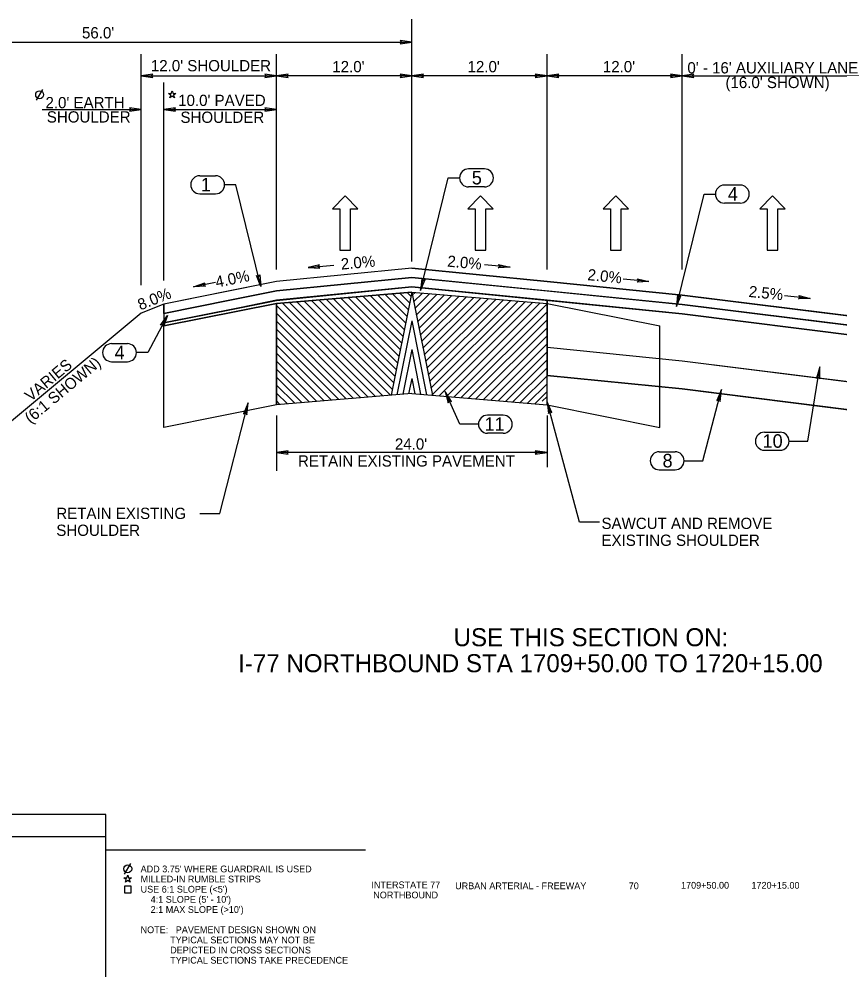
# Model space of a CAD drawing. Extents: x 2003207 to 2014043, y 843846 to 860154.
# Drawn here: x 2013648 to 2013720.8, y 844806 to 844891 of the extents above; entities that cross this region are included whole.
import ezdxf

# ---------------------------------------------------------------- set-up
doc = ezdxf.new("R2010")
doc.units = 0
for name, color, linetype in [('RD_EX_Road', 7, 'Continuous'), ('RD_EX_Road_txCode', 7, 'Continuous'), ('RD_QTY_Base_Course', 7, 'Continuous'), ('RD_QTY_ConcPave', 7, 'Continuous'), ('RD_QTY_Intermediate', 7, 'Continuous'), ('RD_QTY_PermVeg', 7, 'Continuous'), ('RD_QTY_Surf_Course', 7, 'Continuous'), ('RD_SHT_Bndy', 7, 'Continuous'), ('RD_SHT_TX', 7, 'Continuous'), ('RD_TX_Misc2', 7, 'Continuous'), ('RD_TX_TypSect', 7, 'Continuous')]:
    doc.layers.add(name, color=color, linetype=linetype)

msp = doc.modelspace()

# ---------------------------------------------------------------- linework, layer by layer
at = {"layer": 'RD_EX_Road'}
for p, q in [((2013682.86, 844866.75), (2013670.86, 844865.75)), ((2013682.86, 844867.226), (2013679.704, 844866.91)), ((2013680.493, 844866.553), (2013682.432, 844864.613)), ((2013682.86, 844866.75), (2013681.03, 844857.602)), ((2013681.145, 844866.607), (2013682.55, 844865.202)), ((2013681.798, 844866.662), (2013682.668, 844865.792)), ((2013682.451, 844866.716), (2013682.786, 844866.381)), ((2013682.86, 844866.75), (2013684.689, 844857.602)), ((2013682.86, 844866.75), (2013694.86, 844865.75)), ((2013682.913, 844866.483), (2013683.156, 844866.725)), ((2013683.031, 844865.894), (2013683.809, 844866.671)), ((2013683.149, 844865.304), (2013684.461, 844866.617)), ((2013683.267, 844864.715), (2013685.114, 844866.562)), ((2013670.86, 844865.75), (2013660.86, 844863.75)), ((2013670.86, 844856.754), (2013670.86, 844865.75)), ((2013671.355, 844865.791), (2013679.658, 844857.487)), ((2013672.007, 844865.846), (2013680.311, 844857.542)), ((2013672.66, 844865.9), (2013680.964, 844857.596)), ((2013673.313, 844865.955), (2013681.136, 844858.131)), ((2013673.965, 844866.009), (2013681.254, 844858.721)), ((2013674.618, 844866.063), (2013681.372, 844859.31)), ((2013675.271, 844866.118), (2013681.49, 844859.899)), ((2013675.924, 844866.172), (2013681.607, 844860.488)), ((2013676.576, 844866.226), (2013681.725, 844861.078)), ((2013677.229, 844866.281), (2013681.843, 844861.667)), ((2013677.882, 844866.335), (2013681.961, 844862.256)), ((2013678.534, 844866.39), (2013682.079, 844862.845)), ((2013679.187, 844866.444), (2013682.197, 844863.435)), ((2013679.84, 844866.498), (2013682.315, 844864.024)), ((2013683.385, 844864.126), (2013685.767, 844866.508)), ((2013683.503, 844863.537), (2013686.419, 844866.453)), ((2013683.62, 844862.947), (2013687.072, 844866.399)), ((2013683.738, 844862.358), (2013687.725, 844866.345)), ((2013683.856, 844861.769), (2013688.378, 844866.29)), ((2013683.974, 844861.179), (2013689.03, 844866.236)), ((2013684.092, 844860.59), (2013689.683, 844866.182)), ((2013684.21, 844860.001), (2013690.336, 844866.127)), ((2013684.327, 844859.412), (2013690.988, 844866.073)), ((2013684.445, 844858.822), (2013691.641, 844866.018)), ((2013684.563, 844858.233), (2013692.294, 844865.964)), ((2013684.681, 844857.644), (2013692.947, 844865.91)), ((2013685.295, 844857.551), (2013693.599, 844865.855)), ((2013685.935, 844857.483), (2013694.252, 844865.801)), ((2013686.601, 844857.442), (2013694.905, 844865.746)), ((2013694.86, 844856.754), (2013694.86, 844865.75)), ((2013694.86, 844865.75), (2013704.86, 844863.75)), ((2013670.86, 844865.579), (2013679.006, 844857.433)), ((2013670.86, 844864.872), (2013678.353, 844857.379)), ((2013687.254, 844857.388), (2013694.86, 844864.994)), ((2013670.86, 844864.165), (2013677.7, 844857.324)), ((2013682.86, 844864.201), (2013681.549, 844857.645)), ((2013682.86, 844864.201), (2013684.171, 844857.645)), ((2013687.906, 844857.334), (2013694.86, 844864.287)), ((2013660.86, 844854.754), (2013660.86, 844863.75)), ((2013670.86, 844863.458), (2013677.048, 844857.27)), ((2013688.559, 844857.279), (2013694.86, 844863.58)), ((2013704.86, 844854.754), (2013704.86, 844863.75)), ((2013670.86, 844862.751), (2013676.395, 844857.215)), ((2013689.212, 844857.225), (2013694.86, 844862.873)), ((2013670.86, 844862.044), (2013675.742, 844857.161)), ((2013682.86, 844861.651), (2013682.067, 844857.688)), ((2013682.86, 844861.651), (2013683.652, 844857.688)), ((2013689.864, 844857.171), (2013694.86, 844862.166)), ((2013690.517, 844857.116), (2013694.86, 844861.459)), ((2013670.86, 844861.336), (2013675.089, 844857.107)), ((2013670.86, 844860.629), (2013674.437, 844857.052)), ((2013691.17, 844857.062), (2013694.86, 844860.752)), ((2013670.86, 844859.922), (2013673.784, 844856.998)), ((2013691.823, 844857.007), (2013694.86, 844860.045)), ((2013670.86, 844859.215), (2013673.131, 844856.944)), ((2013682.86, 844859.102), (2013682.586, 844857.731)), ((2013682.86, 844859.102), (2013683.134, 844857.731)), ((2013692.475, 844856.953), (2013694.86, 844859.337)), ((2013670.86, 844858.508), (2013672.479, 844856.889)), ((2013693.128, 844856.899), (2013694.86, 844858.63)), ((2013670.86, 844857.801), (2013671.826, 844856.835)), ((2013682.86, 844857.754), (2013670.86, 844856.754)), ((2013682.86, 844857.754), (2013694.86, 844856.754)), ((2013693.781, 844856.844), (2013694.86, 844857.923)), ((2013694.433, 844857.065), (2013694.86, 844857.491)), ((2013670.86, 844856.754), (2013660.86, 844854.754)), ((2013670.86, 844857.094), (2013671.173, 844856.78)), ((2013694.86, 844856.754), (2013704.86, 844854.754))]:
    msp.add_line(p, q, dxfattribs=at)
msp.add_lwpolyline([(2013660.86, 844863.75), (2013670.86, 844865.75), (2013670.86, 844856.754), (2013660.86, 844854.754)], close=True, dxfattribs=at)
at = {"layer": 'RD_EX_Road_txCode'}
msp.add_line((2013657.384, 844815.107), (2013657.95, 844816.05), dxfattribs=at)
for points in [[(2013657.335, 844814.786), (2013657.589, 844814.786), (2013657.667, 844815.028), (2013657.746, 844814.786), (2013658, 844814.786), (2013657.795, 844814.637), (2013657.873, 844814.395), (2013657.667, 844814.544), (2013657.462, 844814.395), (2013657.54, 844814.637)], [(2013657.367, 844813.452), (2013657.967, 844813.452), (2013657.967, 844814.052), (2013657.367, 844814.052)]]:
    msp.add_lwpolyline(points, close=True, dxfattribs=at)
msp.add_circle((2013657.667, 844815.578), 0.35, dxfattribs=at)
at = {"layer": 'RD_QTY_Base_Course'}
for p, q in [((2013694.86, 844861.859), (2013694.86, 844859.359)), ((2013694.86, 844859.359), (2013706.86, 844858.159)), ((2013706.86, 844858.159), (2013722.86, 844856.159))]:
    msp.add_line(p, q, dxfattribs=at)
msp.add_lwpolyline([(2013694.86, 844861.859), (2013706.86, 844860.659), (2013722.86, 844858.659), (2013735.36, 844856.159), (2013735.36, 844853.659), (2013722.86, 844856.159), (2013706.86, 844858.159), (2013694.86, 844859.359)], close=True, dxfattribs=at)
at = {"layer": 'RD_QTY_ConcPave'}
for p, q in [((2013694.86, 844867.692), (2013706.86, 844866.492)), ((2013660.86, 844865.692), (2013660.86, 844864.025)), ((2013694.86, 844861.859), (2013706.86, 844860.659)), ((2013706.86, 844860.659), (2013722.86, 844858.659))]:
    msp.add_line(p, q, dxfattribs=at)
msp.add_lwpolyline([(2013694.86, 844866.026), (2013694.86, 844861.859), (2013706.86, 844860.659), (2013722.86, 844858.659), (2013734.86, 844856.259), (2013734.86, 844860.425), (2013722.86, 844862.826), (2013706.86, 844864.826)], close=True, dxfattribs=at)
at = {"layer": 'RD_QTY_Intermediate'}
for p, q in [((2013682.86, 844868.059), (2013670.86, 844866.859)), ((2013682.86, 844868.059), (2013694.86, 844866.859)), ((2013670.86, 844866.859), (2013660.86, 844864.859)), ((2013682.86, 844867.226), (2013670.86, 844866.026)), ((2013682.86, 844866.75), (2013670.86, 844865.75)), ((2013682.86, 844867.226), (2013694.86, 844866.026)), ((2013682.86, 844866.75), (2013694.86, 844865.75)), ((2013694.86, 844866.859), (2013706.86, 844865.659)), ((2013670.86, 844866.025), (2013660.86, 844864.025)), ((2013670.86, 844865.75), (2013660.86, 844863.75)), ((2013670.86, 844865.75), (2013670.86, 844865.75)), ((2013694.86, 844866.026), (2013694.86, 844865.75)), ((2013694.86, 844866.026), (2013706.86, 844864.826)), ((2013660.86, 844864.859), (2013660.86, 844864.025)), ((2013706.86, 844865.659), (2013722.86, 844863.659)), ((2013660.86, 844864.025), (2013660.86, 844863.75)), ((2013706.86, 844864.826), (2013722.86, 844862.826))]:
    msp.add_line(p, q, dxfattribs=at)
for points in [[(2013670.86, 844866.025), (2013682.86, 844867.226), (2013706.86, 844864.826), (2013722.86, 844862.826), (2013734.86, 844860.425), (2013734.86, 844861.259), (2013722.86, 844863.659), (2013706.86, 844865.659), (2013682.86, 844868.059), (2013670.86, 844866.859), (2013666.86, 844866.059), (2013660.86, 844864.859), (2013660.86, 844864.026), (2013666.86, 844865.225)], [(2013670.86, 844865.75), (2013682.86, 844866.75), (2013694.86, 844865.75), (2013694.86, 844866.026), (2013682.86, 844867.226), (2013670.86, 844866.026), (2013666.86, 844865.226), (2013660.86, 844864.026), (2013660.86, 844863.75)]]:
    msp.add_lwpolyline(points, close=True, dxfattribs=at)
at = {"layer": 'RD_QTY_PermVeg'}
for p, q in [((2013658.86, 844864.892), (2013626.86, 844838.225)), ((2013660.86, 844865.692), (2013658.86, 844864.892))]:
    msp.add_line(p, q, dxfattribs=at)
at = {"layer": 'RD_QTY_Surf_Course'}
for p, q in [((2013682.86, 844868.892), (2013670.86, 844867.692)), ((2013682.86, 844868.892), (2013694.86, 844867.692)), ((2013670.86, 844867.692), (2013660.86, 844865.692)), ((2013706.86, 844866.492), (2013722.86, 844864.492)), ((2013660.86, 844864.859), (2013660.86, 844865.692))]:
    msp.add_line(p, q, dxfattribs=at)
msp.add_lwpolyline([(2013694.86, 844866.859), (2013706.86, 844865.659), (2013722.86, 844863.659), (2013734.86, 844861.259), (2013734.86, 844862.092), (2013722.86, 844864.492), (2013706.86, 844866.492), (2013694.86, 844867.692), (2013682.86, 844868.892), (2013670.86, 844867.692), (2013666.86, 844866.892), (2013660.86, 844865.692), (2013660.86, 844864.859), (2013666.86, 844866.059), (2013670.86, 844866.859), (2013682.86, 844868.059)], close=True, dxfattribs=at)
at = {"layer": 'RD_SHT_Bndy'}
for p, q in [((2013655.721, 844820.41), (2013615.721, 844820.41)), ((2013655.721, 844818.41), (2013655.721, 844820.41)), ((2013655.721, 844818.41), (2013615.721, 844818.41)), ((2013655.721, 844805.992), (2013655.721, 844818.41)), ((2013678.755, 844817.242), (2013655.755, 844817.242))]:
    msp.add_line(p, q, dxfattribs=at)
at = {"layer": 'RD_TX_Misc2'}
for p, q in [((2013689.304, 844877.692), (2013687.904, 844877.692)), ((2013664.06, 844877.077), (2013665.46, 844877.077)), ((2013689.304, 844876.092), (2013687.904, 844876.092)), ((2013711.998, 844876.255), (2013710.598, 844876.255)), ((2013664.06, 844875.477), (2013665.46, 844875.477)), ((2013711.998, 844874.655), (2013710.598, 844874.655)), ((2013656.233, 844862.182), (2013657.633, 844862.182)), ((2013656.233, 844860.582), (2013657.633, 844860.582)), ((2013690.98, 844855.835), (2013689.58, 844855.835)), ((2013690.98, 844854.235), (2013689.58, 844854.235)), ((2013714.144, 844854.326), (2013715.544, 844854.326)), ((2013704.821, 844852.585), (2013706.221, 844852.585)), ((2013714.144, 844852.726), (2013715.544, 844852.726)), ((2013704.821, 844850.985), (2013706.221, 844850.985))]:
    msp.add_line(p, q, dxfattribs=at)
for centre, start, end in [((2013687.904, 844876.892), 90, 270), ((2013689.304, 844876.892), 270, 90), ((2013664.06, 844876.277), 90, 270), ((2013665.46, 844876.277), 270, 90), ((2013710.598, 844875.455), 90, 270), ((2013711.998, 844875.455), 270, 90), ((2013656.233, 844861.382), 90, 270), ((2013657.633, 844861.382), 270, 90), ((2013689.58, 844855.035), 90, 270), ((2013690.98, 844855.035), 270, 90), ((2013714.144, 844853.526), 90, 270), ((2013715.544, 844853.526), 270, 90), ((2013704.821, 844851.785), 90, 270), ((2013706.221, 844851.785), 270, 90)]:
    msp.add_arc(centre, 0.8, start, end, dxfattribs=at)
at = {"layer": 'RD_TX_TypSect'}
for p, q in [((2013682.86, 844869.482), (2013682.86, 844890.976)), ((2013626.86, 844888.924), (2013682.86, 844888.924)), ((2013658.86, 844867.384), (2013658.86, 844887.863)), ((2013670.86, 844868.751), (2013670.86, 844887.863)), ((2013694.86, 844868.751), (2013694.86, 844887.863)), ((2013706.86, 844868.751), (2013706.86, 844887.863)), ((2013658.86, 844885.956), (2013670.86, 844885.956)), ((2013660.86, 844867.787), (2013660.86, 844885.363)), ((2013682.86, 844885.956), (2013670.86, 844885.956)), ((2013670.86, 844885.956), (2013670.86, 844885.956)), ((2013694.86, 844885.956), (2013682.86, 844885.956)), ((2013706.86, 844885.956), (2013694.86, 844885.956)), ((2013706.86, 844885.956), (2013722.86, 844885.956)), ((2013649.566, 844883.794), (2013650.132, 844884.737)), ((2013650.073, 844882.956), (2013658.86, 844882.956)), ((2013660.86, 844882.956), (2013670.86, 844882.956)), ((2013673.669, 844868.938), (2013675.948, 844869.146)), ((2013691.584, 844868.965), (2013689.305, 844869.173)), ((2013665.461, 844867.607), (2013663.51, 844867.217)), ((2013703.894, 844867.685), (2013701.618, 844867.912)), ((2013718.212, 844866.191), (2013715.936, 844866.419)), ((2013670.86, 844855.813), (2013670.86, 844850.894)), ((2013694.86, 844855.813), (2013694.86, 844851.208)), ((2013694.86, 844852.526), (2013670.86, 844852.526))]:
    msp.add_line(p, q, dxfattribs=at)
for points in [[(2013682.86, 844888.924), (2013681.821, 844889.074), (2013681.981, 844888.924), (2013681.821, 844888.775)], [(2013658.86, 844885.956), (2013659.898, 844885.806), (2013659.739, 844885.956), (2013659.898, 844886.106)], [(2013670.86, 844885.956), (2013669.821, 844886.106), (2013669.981, 844885.956), (2013669.821, 844885.806)], [(2013670.86, 844885.956), (2013671.898, 844885.806), (2013671.739, 844885.956), (2013671.898, 844886.106)], [(2013682.86, 844885.956), (2013681.821, 844886.106), (2013681.981, 844885.956), (2013681.821, 844885.806)], [(2013682.86, 844885.956), (2013683.898, 844885.806), (2013683.739, 844885.956), (2013683.898, 844886.106)], [(2013694.86, 844885.956), (2013693.821, 844886.106), (2013693.981, 844885.956), (2013693.821, 844885.806)], [(2013694.86, 844885.956), (2013695.898, 844885.806), (2013695.739, 844885.956), (2013695.898, 844886.106)], [(2013706.86, 844885.956), (2013705.821, 844886.106), (2013705.981, 844885.956), (2013705.821, 844885.806)], [(2013706.86, 844885.956), (2013707.898, 844885.806), (2013707.739, 844885.956), (2013707.898, 844886.106)], [(2013661.275, 844884.383), (2013661.529, 844884.383), (2013661.608, 844884.625), (2013661.686, 844884.383), (2013661.941, 844884.383), (2013661.735, 844884.234), (2013661.814, 844883.992), (2013661.608, 844884.141), (2013661.402, 844883.992), (2013661.481, 844884.234)], [(2013658.86, 844882.956), (2013657.821, 844883.106), (2013657.981, 844882.956), (2013657.821, 844882.806)], [(2013660.86, 844882.956), (2013661.898, 844882.806), (2013661.739, 844882.956), (2013661.898, 844883.106)], [(2013670.86, 844882.956), (2013669.821, 844883.106), (2013669.981, 844882.956), (2013669.821, 844882.806)], [(2013676.482, 844870.484), (2013677.442, 844870.484), (2013677.442, 844874.153), (2013678.093, 844874.153), (2013676.962, 844875.284), (2013675.83, 844874.153), (2013676.482, 844874.153)], [(2013688.482, 844870.484), (2013689.442, 844870.484), (2013689.442, 844874.153), (2013690.093, 844874.153), (2013688.962, 844875.284), (2013687.83, 844874.153), (2013688.482, 844874.153)], [(2013700.482, 844870.484), (2013701.442, 844870.484), (2013701.442, 844874.153), (2013702.093, 844874.153), (2013700.962, 844875.284), (2013699.83, 844874.153), (2013700.482, 844874.153)], [(2013714.38, 844870.484), (2013715.34, 844870.484), (2013715.34, 844874.153), (2013715.991, 844874.153), (2013714.86, 844875.284), (2013713.728, 844874.153), (2013714.38, 844874.153)], [(2013673.669, 844868.938), (2013674.717, 844868.883), (2013674.544, 844869.018), (2013674.69, 844869.182)], [(2013691.584, 844868.965), (2013690.535, 844868.911), (2013690.708, 844869.045), (2013690.563, 844869.209)], [(2013669.477, 844867.257), (2013669.084, 844868.231), (2013669.268, 844868.111), (2013669.375, 844868.302)], [(2013663.51, 844867.217), (2013664.499, 844867.567), (2013664.372, 844867.389), (2013664.558, 844867.273)], [(2013683.65, 844866.902), (2013684.043, 844867.875), (2013683.859, 844867.755), (2013683.751, 844867.946)], [(2013703.894, 844867.685), (2013702.846, 844867.639), (2013703.02, 844867.772), (2013702.876, 844867.937)], [(2013706.344, 844865.464), (2013706.736, 844866.437), (2013706.553, 844866.318), (2013706.445, 844866.509)], [(2013718.212, 844866.191), (2013717.164, 844866.145), (2013717.338, 844866.279), (2013717.194, 844866.444)], [(2013661.181, 844864.681), (2013660.829, 844863.692), (2013660.771, 844863.903), (2013660.564, 844863.832)], [(2013719.071, 844860.12), (2013718.758, 844859.118), (2013718.931, 844859.252), (2013719.054, 844859.07)], [(2013710.349, 844858.101), (2013709.939, 844857.135), (2013710.125, 844857.251), (2013710.229, 844857.059)], [(2013685.817, 844857.927), (2013686.102, 844856.918), (2013686.174, 844857.125), (2013686.376, 844857.04)], [(2013668.35, 844856.918), (2013667.949, 844855.948), (2013668.134, 844856.066), (2013668.24, 844855.874)], [(2013694.86, 844857.03), (2013694.984, 844855.988), (2013695.087, 844856.181), (2013695.274, 844856.065)], [(2013670.86, 844852.526), (2013671.898, 844852.376), (2013671.739, 844852.526), (2013671.898, 844852.676)], [(2013694.86, 844852.526), (2013693.821, 844852.676), (2013693.981, 844852.526), (2013693.821, 844852.376)]]:
    msp.add_lwpolyline(points, close=True, dxfattribs=at)
for points in [[(2013683.65, 844866.902), (2013686.095, 844876.892), (2013687.104, 844876.892)], [(2013669.477, 844867.257), (2013667.269, 844876.277), (2013666.26, 844876.277)], [(2013706.344, 844865.464), (2013708.789, 844875.455), (2013709.798, 844875.455)], [(2013661.181, 844864.681), (2013659.442, 844861.382), (2013658.433, 844861.382)], [(2013716.344, 844853.526), (2013718.009, 844853.526), (2013719.071, 844860.12)], [(2013707.021, 844851.785), (2013708.687, 844851.785), (2013710.349, 844858.101)], [(2013688.78, 844855.035), (2013687.114, 844855.035), (2013685.817, 844857.927)], [(2013664.064, 844847.108), (2013665.839, 844847.108), (2013668.35, 844856.918)], [(2013699.505, 844846.327), (2013697.73, 844846.327), (2013694.86, 844857.03)]]:
    msp.add_lwpolyline(points, dxfattribs=at)
msp.add_circle((2013649.849, 844884.266), 0.35, dxfattribs=at)

# ---------------------------------------------------------------- texts
at = {"layer": 'RD_EX_Road_txCode'}
for s, height, p in [('USE THIS SECTION ON:', 1.6, (2013686.571, 844835.331)), ('I-77 NORTHBOUND STA 1709+50.00 TO 1720+15.00', 1.6, (2013667.459, 844833.025)), ("ADD 3.75' WHERE GUARDRAIL IS USED", 0.6, (2013658.808, 844815.268)), ('MILLED-IN RUMBLE STRIPS', 0.6, (2013658.808, 844814.368)), ("USE 6:1 SLOPE (<5')", 0.6, (2013658.808, 844813.468)), ("    4:1 SLOPE (5' - 10')", 0.6, (2013658.808, 844812.568)), ("    2:1 MAX SLOPE (>10')", 0.6, (2013658.808, 844811.668)), ('NOTE:   PAVEMENT DESIGN SHOWN ON', 0.6, (2013658.808, 844809.868)), (' TYPICAL SECTIONS MAY NOT BE ', 0.6, (2013661.208, 844808.968)), (' DEPICTED IN CROSS SECTIONS', 0.6, (2013661.208, 844808.068)), (' TYPICAL SECTIONS TAKE PRECEDENCE', 0.6, (2013661.208, 844807.168))]:
    msp.add_text(s, height=height, dxfattribs=at).set_placement(p)
at = {"layer": 'RD_SHT_TX'}
for s, p in [('INTERSTATE 77', (2013679.283, 844813.853)), ('URBAN ARTERIAL - FREEWAY', (2013686.711, 844813.768)), ('70', (2013702.109, 844813.768)), ('1709+50.00', (2013706.749, 844813.817)), ('1720+15.00', (2013712.999, 844813.817)), ('NORTHBOUND', (2013679.448, 844812.953))]:
    msp.add_text(s, height=0.6, dxfattribs=at).set_placement(p)
at = {"layer": 'RD_TX_Misc2'}
for s, p in [('1', (2013664.148, 844875.692)), ('5', (2013688.186, 844876.308)), ('4', (2013710.903, 844874.87)), ('4', (2013656.501, 844860.797)), ('11', (2013689.319, 844854.45)), ('10', (2013713.981, 844852.942)), ('8', (2013705.112, 844851.201))]:
    msp.add_text(s, height=1.2, dxfattribs=at).set_placement(p)
at = {"layer": 'RD_TX_TypSect'}
for s, p in [("56.0'", (2013653.607, 844889.268)), ("12.0' SHOULDER", (2013659.719, 844886.348)), ("12.0'", (2013675.814, 844886.264)), ("12.0'", (2013687.814, 844886.264)), ("12.0'", (2013699.814, 844886.264)), ("0' - 16' AUXILIARY LANE", (2013707.314, 844886.16)), ("(16.0' SHOWN)", (2013710.692, 844884.86)), ("2.0' EARTH", (2013650.369, 844883.069)), ("10.0' PAVED", (2013662.14, 844883.271)), ('SHOULDER', (2013650.487, 844881.802)), ('SHOULDER', (2013662.344, 844881.771)), ("24.0'", (2013681.366, 844852.772)), ('RETAIN EXISTING PAVEMENT', (2013672.768, 844851.272)), ('RETAIN EXISTING ', (2013651.329, 844846.621)), ('SAWCUT AND REMOVE', (2013699.693, 844845.735)), ('SHOULDER', (2013651.329, 844845.121)), ('EXISTING SHOULDER', (2013699.693, 844844.235))]:
    msp.add_text(s, height=1, dxfattribs=at).set_placement(p)
for s, rotation, p in [('2.0%', 5.2184, (2013676.62, 844868.745)), ('2.0%', 354.7816, (2013685.986, 844869.021)), ('4.0%', 11.30993, (2013665.548, 844867.152)), ('2.0%', 354.28941, (2013698.417, 844867.822)), ('8.0%', 21.80141, (2013658.789, 844865.122)), ('2.5%', 354.28941, (2013712.719, 844866.331)), ('VARIES', 39.80557, (2013649.058, 844856.999)), ('(6:1 SHOWN)', 39.80557, (2013649.044, 844855.036))]:
    msp.add_text(s, height=1, rotation=rotation, dxfattribs=at).set_placement(p)

doc.saveas('drawing.dxf')
